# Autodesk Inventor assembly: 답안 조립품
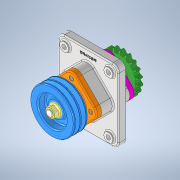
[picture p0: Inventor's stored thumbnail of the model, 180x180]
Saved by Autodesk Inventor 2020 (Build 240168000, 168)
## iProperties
Created: 2021-07
Part Number: 답안 조립품
Document SubType Name: Assembly
Designer: Owner
Author: Owner
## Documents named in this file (16)
- C:\Users\Owner\Desktop\710707V1013\710707V1013\답안 조립품.iam
- C:\Users\Owner\Desktop\710707V1013\710707V1013\본체.ipt
- C:\Users\Owner\Desktop\710707V1013\710707V1013\M16 너트.ipt
- C:\Users\Owner\Desktop\710707V1013\710707V1013\V-벨트풀리.ipt
- C:\Users\Owner\Desktop\710707V1013\710707V1013\멈춤나사 M4.ipt
- C:\Users\Owner\Desktop\710707V1013\710707V1013\베어링 6206.ipt
- C:\Users\Owner\Desktop\710707V1013\710707V1013\볼트 M6.ipt
- C:\Users\Owner\Desktop\710707V1013\710707V1013\부시.ipt
- C:\Users\Owner\Desktop\710707V1013\710707V1013\오일실 30x42x8.ipt
- C:\Users\Owner\Desktop\710707V1013\710707V1013\오일실 30x45x8.ipt
- C:\Users\Owner\Desktop\710707V1013\710707V1013\체인 스프로킷.ipt
- C:\Users\Owner\Desktop\710707V1013\710707V1013\축.ipt
- C:\Users\Owner\Desktop\710707V1013\710707V1013\커버A.ipt
- C:\Users\Owner\Desktop\710707V1013\710707V1013\커버B.ipt
- C:\Users\Owner\Desktop\710707V1013\710707V1013\키 6x6x18.ipt
- C:\Users\Owner\Desktop\710707V1013\710707V1013\키 6x6x20.ipt
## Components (3 placed, 2 different names)
1. M16 너트:1
2. V-벨트풀리:1 — 각도:2
3. M16 너트:2
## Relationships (1: Angle 1)
- 각도:2 [Angle]: V-벨트풀리:1
